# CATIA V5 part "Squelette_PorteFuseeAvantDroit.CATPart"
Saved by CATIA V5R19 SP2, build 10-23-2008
Part number: Squelette_PorteFuseeAvantDroit
Bounding box of the stored display mesh (mm): x -33.824 to 7.506, y -233.644 to -186.535, z -160.612 to -121.676
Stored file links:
  E:\Mes documents\03_Ressources pédagogiques\01_Catia\Buggy Dassault\SchemaCinematiqueFinal\Squelette_PorteFuseeAvantDroit.CATPart
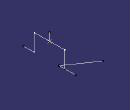
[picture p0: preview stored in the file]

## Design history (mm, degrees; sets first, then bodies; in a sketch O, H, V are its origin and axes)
AxisSystem1: origin (0, 0, 0), X (1, 0, 0), Y (0, 1, 0), Z (0, 0, 1)
Set1
  Point1 to Point11: stored without definition
  Line1 to Line3: stored without definition
  Plane1: stored without definition
  Sketch1 on Plane1, origin (1.5118, 0.0225, -0.0264), H (-0.0149, 0.9999, 0), V (0.0174, 0.0003, 0.9998)
    line L1 (-233.7304, 143.9301) -> (-224.1181, 143.9301)
    point P1 (-233.7304, 143.9301)
    line L2 (-224.1181, 143.9301) -> (-224.1181, 128.7204)
    line L3 (-224.1181, 128.7204) -> (-196.496, 128.7204)
    line L4 (-196.496, 128.7204) -> (-196.496, 143.5095)
    line L5 (-196.496, 143.5095) -> (-186.6158, 143.5095)
    point P6 (-186.6158, 143.5095)
    reference projected point E1 (-186.6158, 143.5095) from Point3
    reference projected point E2 (-233.7304, 143.9301) from Point9
    projected point E3 (-210.307, 128.7204) from Point12
    line L6 (-196.496, 143.5095) -> (-201.6467, 143.5095)
    horizontal: L1 H, L3 H, L5 H, L6 H
    vertical: L2 V, L4 V
    coincidence: P6 E1, P1 E2
    midpoint: E3 L3
  Point12 "Centre": stored without definition
  MultiSel1
Body1 (main body)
